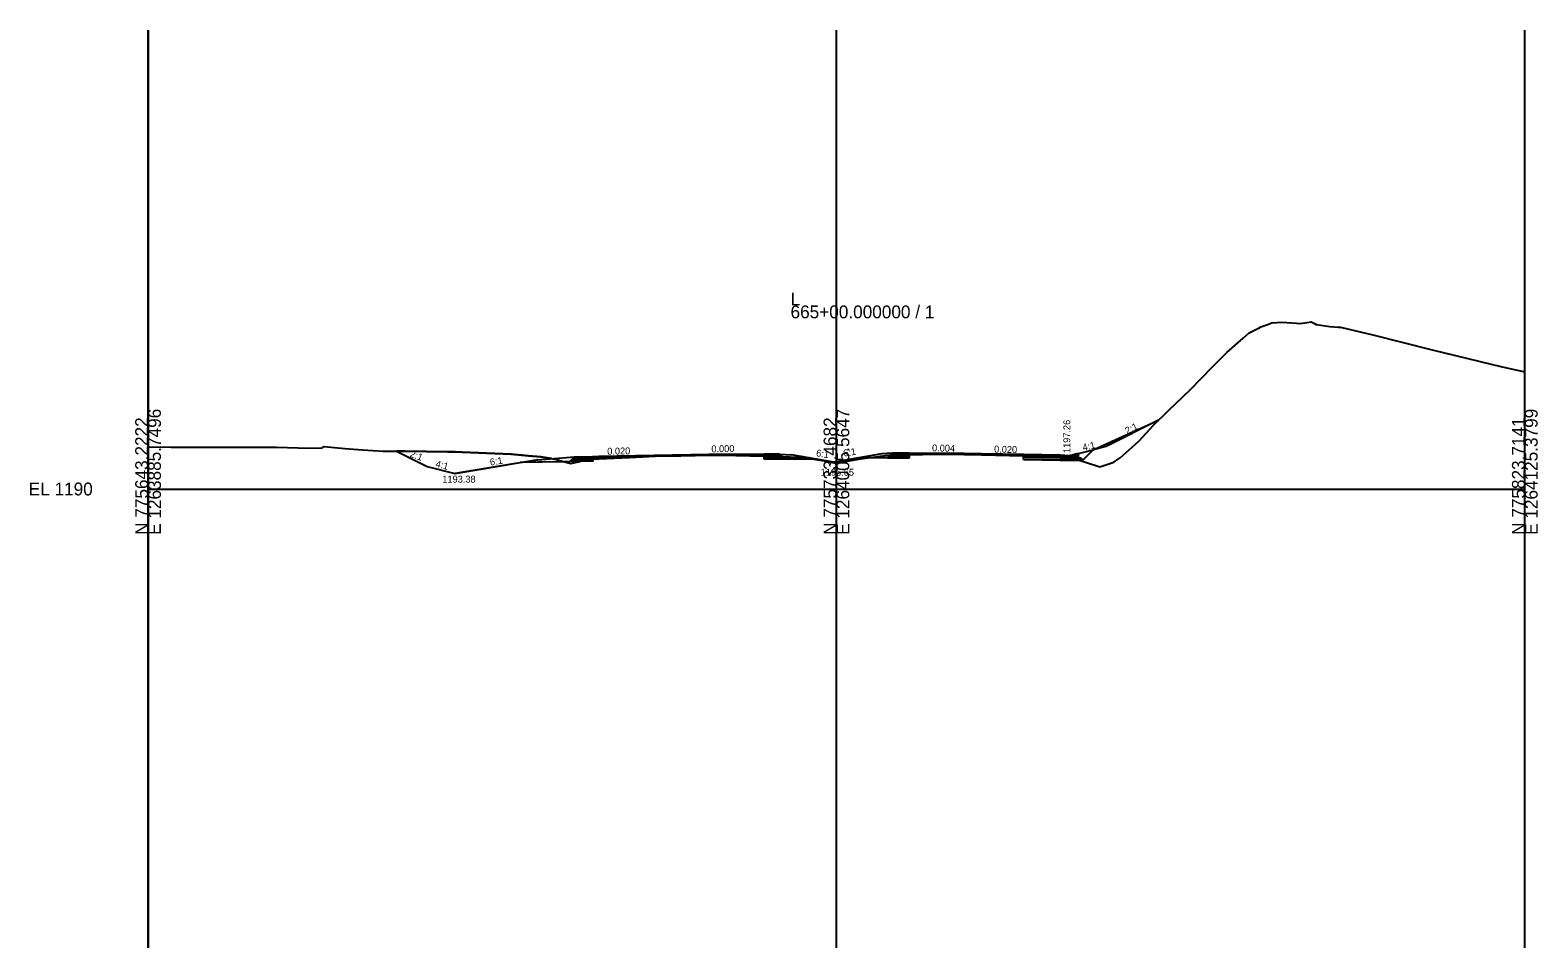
# Model space of a CAD drawing. Extents: x -41 to 1262860, y -100 to 777489.
# Drawn here: x -25.7 to 302.8, y 1130 to 1330 of the extents above; entities that cross this region are included whole.
import ezdxf

# ---------------------------------------------------------------- set-up
doc = ezdxf.new("R2010")
doc.units = 0
for name, color, linetype in [('Exist Cross Section Cell', 7, 'Continuous'), ('Exist XS Center Line Elevation Label', 7, 'Continuous'), ('Exist XS Ground Line', 7, 'Continuous'), ('Prop CMT Pvmt Course 1', 7, 'Continuous'), ('Prop CMT Pvmt Milling', 7, 'Continuous'), ('Prop CMT Pvmt Surface', 7, 'Continuous'), ('Prop CMT Shld Paved Course 1', 7, 'Continuous'), ('Prop CMT Shld Paved Course 2', 7, 'Continuous'), ('Prop CMT Shld Paved Course 4', 7, 'Continuous'), ('Prop CMT Subgrade Earthwork', 7, 'Continuous'), ('Prop XS Ditch Standard Text', 7, 'Continuous'), ('Prop XS Earthwork Shape', 7, 'Continuous'), ('Prop XS Elevation Labels', 7, 'Continuous'), ('Prop XS Exc Vertical Line 1', 7, 'Continuous'), ('Prop XS Exc Vertical Line 2', 7, 'Continuous'), ('Prop XS Exc Vertical Line 3', 7, 'Continuous'), ('Prop XS Finish Grade', 7, 'Continuous'), ('Prop XS Label Text', 7, 'Continuous'), ('Prop XS SE Text', 7, 'Continuous'), ('Prop XS Side Slope Text', 7, 'Continuous'), ('Scratch_Level_4', 7, 'Continuous'), ('Scratch_Level_5', 7, 'Continuous'), ('Scratch_Level_6', 7, 'Continuous'), ('Typical Curb CELL', 7, 'Continuous')]:
    doc.layers.add(name, color=color, linetype=linetype)

msp = doc.modelspace()

# ---------------------------------------------------------------- linework, layer by layer
at = {"layer": 'Exist Cross Section Cell'}
for p, q in [((150, 1230), (150, 1270)), ((0, 1230), (150, 1230)), ((150, 1230), (300, 1230))]:
    msp.add_line(p, q, dxfattribs=at)
at = {"layer": 'Exist XS Ground Line'}
msp.add_lwpolyline([(0, 1239.22), (5.07, 1239.15), (8.88, 1239.1), (19.3, 1239.12), (28.02, 1239.13), (32.7, 1239), (37.88, 1238.88), (38.14, 1239.15), (38.37, 1239.25), (42.85, 1238.82), (46.75, 1238.54), (51.23, 1238.26), (56.13, 1238.21), (65.23, 1238.11), (66.94, 1238.09), (68.44, 1238.02), (79.14, 1237.59), (82.87, 1237.25), (85.57, 1237.04), (88.19, 1236.57), (89.39, 1236.33), (90.27, 1236.06), (92.1, 1235.55), (93.8, 1235.95), (96.4, 1236.61), (97.2, 1236.57), (98.06, 1236.59), (104.9, 1236.86), (110.54, 1237.13), (116.06, 1237.24), (122.43, 1237.38), (128.05, 1237.28), (135.32, 1237.17), (136.53, 1237.13), (138.41, 1237.07), (141.49, 1236.92), (143.73, 1236.76), (147.74, 1236.03), (149.82, 1235.62), (151.22, 1235.88), (155.23, 1236.59), (157.47, 1236.89), (161.09, 1237.34), (162.82, 1237.41), (164.56, 1237.48), (170.55, 1237.57), (176.46, 1237.65), (183.33, 1237.59), (188.86, 1237.57), (192.95, 1237.41), (196.32, 1237.27), (196.9, 1237.22), (198.11, 1237.13), (201.84, 1236.5), (202.8, 1236.28), (204.25, 1235.88), (207.4, 1234.86), (210.26, 1235.77), (210.48, 1235.84), (210.77, 1236.03), (211.8, 1236.82), (214.43, 1239.1), (215.87, 1240.46), (219.16, 1243.96), (222.38, 1247.11), (227.17, 1251.72), (231.9, 1256.57), (235.04, 1259.72), (238.64, 1262.87), (239.95, 1264.04), (240.24, 1264.15), (241.68, 1264.88), (241.98, 1265.03), (242.01, 1265.06), (242.08, 1265.06), (242.29, 1265.27), (242.7, 1265.39), (243.77, 1265.81), (244.9, 1266.25), (247.08, 1266.37), (250.22, 1266.17), (251.12, 1266.1), (253.47, 1266.4), (253.74, 1266.31), (254.2, 1266.07), (254.5, 1265.85), (257.51, 1265.42), (259.33, 1265.3), (259.82, 1265.24), (266.86, 1263.57), (279.8, 1260.31), (295.07, 1256.64), (300, 1255.51)], dxfattribs=at)
at = {"layer": 'Prop CMT Pvmt Course 1'}
for points in [[(96.93, 1236.85), (96.93, 1237.1), (98.24, 1237.13), (122.24, 1237.61), (122.24, 1237.61), (134.24, 1237.62), (134.24, 1237.37), (134.24, 1237.37), (122.24, 1237.36), (122.24, 1237.36), (96.93, 1236.85), (98.24, 1236.88), (98.24, 1236.88)], [(190.75, 1237.25), (190.75, 1237.5), (181.58, 1237.68), (181.58, 1237.68), (177.84, 1237.76), (177.84, 1237.76), (177.84, 1237.76), (165.87, 1237.81), (165.87, 1237.56), (177.84, 1237.51), (177.84, 1237.51), (177.84, 1237.51), (181.58, 1237.43), (181.58, 1237.43), (190.75, 1237.25), (189.84, 1237.27)]]:
    msp.add_lwpolyline(points, dxfattribs=at)
at = {"layer": 'Prop CMT Pvmt Milling'}
for points in [[(134.24, 1237.19), (134.24, 1237.19), (128.05, 1237.28), (128.05, 1237.28), (122.43, 1237.38), (122.24, 1237.38), (122.24, 1237.38), (116.06, 1237.24), (116.06, 1237.24), (110.54, 1237.13), (110.54, 1237.13), (110.54, 1237.13), (104.9, 1236.86), (104.9, 1236.86), (98.24, 1236.6), (98.24, 1236.6)], [(134.24, 1237.19), (134.24, 1237.19), (128.05, 1237.28), (128.05, 1237.28), (123.59, 1237.36), (122.43, 1237.36), (122.43, 1237.36), (122.43, 1237.36), (122.24, 1237.36), (122.24, 1237.36), (116.06, 1237.24), (116.06, 1237.24), (110.54, 1237.12), (110.54, 1237.12), (110.46, 1237.12), (110.46, 1237.12), (104.9, 1236.86), (104.9, 1236.86), (98.24, 1236.6), (98.24, 1236.6)]]:
    msp.add_lwpolyline(points, dxfattribs=at)
at = {"layer": 'Prop CMT Pvmt Surface'}
for p, q in [((92.93, 1237.02), (96.93, 1237.1)), ((96.93, 1237.1), (122.24, 1237.61)), ((122.24, 1237.61), (134.24, 1237.62)), ((134.24, 1237.62), (137.6, 1237.62)), ((162.15, 1237.82), (165.87, 1237.81)), ((165.87, 1237.81), (177.84, 1237.76)), ((177.84, 1237.76), (190.75, 1237.5)), ((190.75, 1237.5), (198.75, 1237.34))]:
    msp.add_line(p, q, dxfattribs=at)
at = {"layer": 'Prop CMT Shld Paved Course 1'}
for p in [(199, 1237.08), (199.01, 1237.08)]:
    msp.add_line(p, (199.01, 1237.08), dxfattribs=at)
for points in [[(92.93, 1237.02), (96.93, 1237.1), (96.93, 1236.85), (96.93, 1236.85), (92.68, 1236.77), (92.68, 1236.77), (92.68, 1236.77), (92.93, 1237.02), (92.93, 1237.02)], [(134.24, 1237.62), (134.24, 1237.62), (134.24, 1237.37), (134.24, 1237.37), (134.24, 1237.37), (137.85, 1237.37), (137.6, 1237.62), (137.6, 1237.62), (134.24, 1237.62)], [(165.87, 1237.81), (162.15, 1237.82), (162.15, 1237.82), (161.9, 1237.57), (165.87, 1237.56), (165.87, 1237.56), (165.87, 1237.56), (165.87, 1237.81), (165.87, 1237.81)], [(198.75, 1237.34), (190.75, 1237.5), (190.75, 1237.25), (190.75, 1237.25), (195.02, 1237.16), (195.02, 1237.16), (198.75, 1237.09), (198.75, 1237.34), (198.75, 1237.34)]]:
    msp.add_lwpolyline(points, dxfattribs=at)
at = {"layer": 'Prop CMT Shld Paved Course 2'}
for p, q in [((190.75, 1237.25), (198.75, 1237.09)), ((190.75, 1236.92), (198.75, 1236.76)), ((198.75, 1237.09), (198.75, 1237.34)), ((198.75, 1236.76), (198.75, 1237.09)), ((199.01, 1237.08), (199, 1237.08))]:
    msp.add_line(p, q, dxfattribs=at)
for points in [[(92.68, 1236.77), (96.93, 1236.85), (96.93, 1236.52), (96.93, 1236.52), (92.34, 1236.43), (92.34, 1236.43), (92.34, 1236.43), (92.68, 1236.77), (92.68, 1236.77)], [(134.24, 1237.37), (128.05, 1237.36), (128.05, 1237.36), (122.43, 1237.36), (122.43, 1237.36), (122.24, 1237.36), (116.06, 1237.24), (116.06, 1237.24), (110.54, 1237.12), (110.54, 1237.12), (110.54, 1237.12), (104.9, 1237.01), (104.9, 1237.01), (98.24, 1236.88), (96.93, 1236.85), (96.93, 1236.59), (97.06, 1236.58), (97.2, 1236.57), (98.24, 1236.6), (98.24, 1236.6), (98.24, 1236.6), (104.9, 1236.86), (104.9, 1236.86), (110.46, 1237.12), (110.46, 1237.12), (110.54, 1237.12), (110.54, 1237.12), (116.06, 1237.24), (116.06, 1237.24), (122.24, 1237.36), (122.24, 1237.36), (122.43, 1237.36), (122.43, 1237.36), (122.43, 1237.36), (123.59, 1237.36), (128.05, 1237.28), (128.05, 1237.28), (134.24, 1237.19), (134.24, 1237.19), (134.24, 1237.19), (134.24, 1237.37), (134.24, 1237.37)], [(134.24, 1237.37), (134.24, 1237.37), (134.24, 1237.04), (134.24, 1237.04), (134.24, 1237.04), (138.19, 1237.04), (137.85, 1237.37), (137.85, 1237.37), (134.23, 1237.37)], [(165.87, 1237.56), (161.9, 1237.57), (161.9, 1237.57), (161.57, 1237.24), (165.87, 1237.22), (165.87, 1237.22), (165.87, 1237.22), (165.87, 1237.56), (165.87, 1237.56)]]:
    msp.add_lwpolyline(points, dxfattribs=at)
msp.add_lwpolyline([(165.87, 1237.56), (165.87, 1237.5), (168.77, 1237.54)], close=True, dxfattribs=at)
at = {"layer": 'Prop CMT Shld Paved Course 4'}
for p, q in [((190.75, 1236.46), (198.75, 1236.3)), ((198.75, 1236.76), (203.25, 1236.76)), ((203.71, 1236.3), (198.75, 1236.3)), ((203.25, 1236.76), (203.71, 1236.3))]:
    msp.add_line(p, q, dxfattribs=at)
for points in [[(92.34, 1236.43), (96.93, 1236.52), (96.93, 1236.06), (96.93, 1236.06), (91.87, 1235.96), (91.87, 1235.96), (91.87, 1235.96), (92.34, 1236.43), (92.34, 1236.43), (92.34, 1236.43), (92.35, 1236.43)], [(134.24, 1237.04), (134.24, 1237.04), (134.24, 1236.58), (134.24, 1236.58), (134.24, 1236.58), (138.64, 1236.58), (138.19, 1237.04), (138.19, 1237.04), (138.19, 1237.04), (138.19, 1237.04), (134.24, 1237.04)], [(165.87, 1237.22), (161.57, 1237.24), (161.57, 1237.24), (161.57, 1237.24), (161.57, 1237.24), (161.11, 1236.78), (165.87, 1236.76), (165.87, 1236.76), (165.87, 1236.76), (165.87, 1237.22), (165.87, 1237.22)]]:
    msp.add_lwpolyline(points, dxfattribs=at)
at = {"layer": 'Prop CMT Subgrade Earthwork'}
for p, q in [((96.93, 1236.06), (81.1, 1235.74)), ((96.93, 1236.06), (96.93, 1236.59)), ((134.24, 1236.58), (134.24, 1237.19)), ((134.24, 1236.58), (145.18, 1236.59)), ((165.87, 1236.76), (154.93, 1236.81)), ((165.87, 1236.76), (165.87, 1237.5)), ((190.75, 1236.46), (190.75, 1237.49)), ((190.75, 1236.46), (198.74, 1236.3)), ((198.75, 1236.3), (203.71, 1236.3)), ((203.71, 1236.3), (205.96, 1238.56))]:
    msp.add_line(p, q, dxfattribs=at)
at = {"layer": 'Prop XS Earthwork Shape'}
for points in [[(202.8, 1236.28), (204.25, 1235.88), (207.4, 1234.86), (210.26, 1235.77), (210.48, 1235.84), (210.77, 1236.03), (211.8, 1236.82), (214.43, 1239.1), (215.87, 1240.46), (219.16, 1243.96), (220.21, 1244.99), (208.75, 1239.26), (205.96, 1238.56), (203.71, 1236.3), (202.73, 1236.3)], [(54.14, 1238.23), (60.83, 1234.88), (66.83, 1233.38), (66.88, 1233.38), (66.93, 1233.38), (81.1, 1235.74), (84.93, 1236.38), (87.92, 1236.62), (85.57, 1237.04), (82.87, 1237.25), (79.14, 1237.59), (68.44, 1238.02), (66.94, 1238.09), (65.23, 1238.11), (56.13, 1238.21)], [(90.72, 1235.94), (81.1, 1235.74), (84.93, 1236.38), (87.92, 1236.62), (88.19, 1236.57), (89.39, 1236.33), (90.27, 1236.06)], [(94.01, 1236), (91.87, 1235.96), (90.72, 1235.94), (92.1, 1235.55), (93.8, 1235.95)], [(94.01, 1236), (96.4, 1236.61), (96.93, 1236.59), (96.93, 1236.06)], [(134.24, 1236.58), (138.64, 1236.58), (138.15, 1237.07), (136.53, 1237.13), (135.32, 1237.17), (134.24, 1237.19)], [(143.73, 1236.76), (144.66, 1236.59), (138.64, 1236.58), (138.15, 1237.07), (138.41, 1237.07), (141.49, 1236.92)], [(144.66, 1236.59), (147.74, 1236.03), (149.82, 1235.62), (151.22, 1235.88), (155.23, 1236.59), (156.8, 1236.8), (154.93, 1236.81), (149.42, 1235.88), (145.18, 1236.59)], [(161.11, 1236.78), (156.8, 1236.8), (157.47, 1236.89), (161.09, 1237.34), (161.69, 1237.36)], [(165.87, 1236.76), (161.11, 1236.78), (161.69, 1237.36), (162.82, 1237.41), (164.56, 1237.48), (165.87, 1237.5)], [(190.75, 1236.46), (190.75, 1237.49), (192.95, 1237.41), (196.32, 1237.27), (196.9, 1237.22), (198.11, 1237.13), (198.75, 1237.02), (201.84, 1236.5), (202.73, 1236.3), (198.74, 1236.3)]]:
    msp.add_lwpolyline(points, close=True, dxfattribs=at)
at = {"layer": 'Prop XS Exc Vertical Line 1'}
msp.add_line((0, 1130), (0, 1330), dxfattribs=at)
at = {"layer": 'Prop XS Exc Vertical Line 2'}
msp.add_line((150, 1130), (150, 1330), dxfattribs=at)
at = {"layer": 'Prop XS Exc Vertical Line 3'}
msp.add_line((300, 1130), (300, 1330), dxfattribs=at)
at = {"layer": 'Prop XS Finish Grade'}
for p, q in [((205.96, 1238.56), (220.21, 1244.99)), ((92.93, 1237.02), (91.87, 1235.96)), ((137.6, 1237.62), (138.64, 1236.58)), ((149.42, 1235.88), (140.24, 1237.41)), ((159.87, 1237.64), (149.42, 1235.88)), ((162.15, 1237.82), (161.11, 1236.78)), ((200.75, 1237.26), (198.75, 1237.34)), ((198.75, 1237.34), (198.75, 1237.02)), ((202.75, 1237.76), (200.75, 1237.26)), ((202.75, 1237.76), (205.96, 1238.56))]:
    msp.add_line(p, q, dxfattribs=at)
for points in [[(54.14, 1238.23), (60.83, 1234.88), (60.83, 1234.88), (60.83, 1234.88), (66.83, 1233.38)], [(84.93, 1236.38), (66.93, 1233.38), (66.88, 1233.38), (66.83, 1233.38)], [(84.93, 1236.38), (84.93, 1236.38), (92.93, 1237.02)], [(137.6, 1237.62), (140.24, 1237.41)], [(162.15, 1237.82), (159.87, 1237.64)]]:
    msp.add_lwpolyline(points, dxfattribs=at)
at = {"layer": 'Scratch_Level_4'}
msp.add_line((300, 1130), (300, 1330), dxfattribs=at)
at = {"layer": 'Scratch_Level_5'}
msp.add_line((137.6, 1237.62), (138.64, 1236.58), dxfattribs=at)
at = {"layer": 'Scratch_Level_6'}
msp.add_line((0, 1330), (0, 1130), dxfattribs=at)
at = {"layer": 'Typical Curb CELL'}
for p, q in [((198.75, 1236.76), (198.75, 1237.34)), ((198.75, 1237.34), (200.75, 1237.26)), ((202.75, 1236.76), (198.75, 1236.76)), ((198.92, 1237.11), (199.01, 1237.23)), ((199.04, 1237.11), (198.92, 1237.11)), ((199.01, 1237.23), (199.04, 1237.11)), ((199.28, 1236.87), (199.34, 1236.98)), ((199.44, 1236.91), (199.28, 1236.87)), ((199.34, 1236.98), (199.44, 1236.91)), ((199.97, 1237.06), (200.05, 1237.18)), ((200.09, 1237.07), (199.97, 1237.06)), ((200.05, 1237.18), (200.09, 1237.07)), ((200.73, 1237.01), (200.79, 1237.13)), ((200.9, 1237.05), (200.73, 1237.01)), ((200.75, 1237.26), (202.75, 1237.76)), ((200.79, 1237.13), (200.9, 1237.05)), ((201.22, 1237.06), (201.3, 1237.18)), ((201.34, 1237.07), (201.22, 1237.06)), ((201.3, 1237.18), (201.34, 1237.07)), ((201.98, 1237.01), (202.04, 1237.13)), ((202.15, 1237.05), (201.98, 1237.01)), ((202.04, 1237.13), (202.15, 1237.05)), ((202.56, 1237.26), (202.58, 1237.17)), ((202.71, 1237.21), (202.56, 1237.26)), ((202.58, 1237.17), (202.71, 1237.21)), ((202.75, 1236.76), (202.75, 1237.76))]:
    msp.add_line(p, q, dxfattribs=at)
for centre in [(198.85, 1237.24), (198.89, 1237), (199.01, 1236.84), (199.18, 1236.98), (199.25, 1237.21), (199.47, 1237.2), (199.62, 1236.92), (199.82, 1237.15), (199.86, 1237.28), (200.11, 1236.85), (200.22, 1237.2), (200.28, 1237.02), (200.34, 1236.99), (200.37, 1237.12), (200.43, 1236.83), (200.45, 1237.11), (200.5, 1237.14), (200.55, 1237.03), (200.66, 1236.87), (200.74, 1237.07), (200.78, 1236.95), (200.94, 1237.05), (200.96, 1237.1), (200.97, 1237.16), (201.03, 1237.02), (201.12, 1236.86), (201.13, 1237.06), (201.18, 1237.22), (201.22, 1237.07), (201.34, 1237.02), (201.48, 1236.89), (201.53, 1237.02), (201.59, 1236.99), (201.62, 1237.12), (201.64, 1237.31), (201.75, 1237.14), (201.79, 1237.03), (201.8, 1236.85), (201.99, 1237.07), (202, 1237.37), (202.02, 1236.97), (202.19, 1237.05), (202.21, 1237.1), (202.38, 1237.44), (202.47, 1237.07), (202.5, 1236.92), (202.57, 1237.47), (202.59, 1237.02), (202.68, 1237.3)]:
    msp.add_circle(centre, 0.00802, dxfattribs=at)

# ---------------------------------------------------------------- texts
at = {"layer": 'Exist Cross Section Cell'}
for s, p in [('L', (140, 1270)), ('665+00.000000 / 1', (140, 1267.2)), ('EL 1190', (-26, 1228.6))]:
    msp.add_text(s, height=2.8, dxfattribs=at).set_placement(p)
for s, p in [('N 775643.2222', (0, 1220)), ('E 1263885.7496', (2.8, 1220)), ('N 775733.4682', (150, 1220)), ('E 1264005.5647', (152.8, 1220)), ('N 775823.7141', (300, 1220)), ('E 1264125.3799', (302.8, 1220))]:
    msp.add_text(s, height=2.8, rotation=90, dxfattribs=at).set_placement(p)
at = {"layer": 'Exist XS Center Line Elevation Label'}
msp.add_text('1195.65', height=1.5, dxfattribs=at).set_placement((146.57, 1232.9))
at = {"layer": 'Prop XS Ditch Standard Text'}
msp.add_text('1193.38', height=1.5, dxfattribs=at).set_placement((64.12, 1231.39))
at = {"layer": 'Prop XS Elevation Labels'}
msp.add_text('1197.26', height=1.5, rotation=90, dxfattribs=at).set_placement((200.95, 1237.83))
at = {"layer": 'Prop XS Label Text'}
for s, rotation, p in [('2:1', 26.5651, (213.34, 1241.91)), ('4:1', 14.0362, (203.81, 1238.26))]:
    msp.add_text(s, height=1.5, rotation=rotation, dxfattribs=at).set_placement(p)
at = {"layer": 'Prop XS SE Text'}
for s, rotation, p in [('0.020', 1.1458, (100.07, 1237.47)), ('0.000', 1.1458, (122.76, 1237.99)), ('0.004', 358.8542, (170.82, 1238.21)), ('0.020', 358.8542, (184.34, 1237.94))]:
    msp.add_text(s, height=1.5, rotation=rotation, dxfattribs=at).set_placement(p)
at = {"layer": 'Prop XS Side Slope Text'}
for s, rotation, p in [('6:1', 350.5377, (145.49, 1237.16)), ('6:1', 9.4623, (151.62, 1237.04)), ('2:1', 339.7612, (56.92, 1237.07)), ('4:1', 345.9638, (62.54, 1234.82)), ('6:1', 9.4623, (74.62, 1235.09))]:
    msp.add_text(s, height=1.5, rotation=rotation, dxfattribs=at).set_placement(p)

doc.saveas('drawing.dxf')
